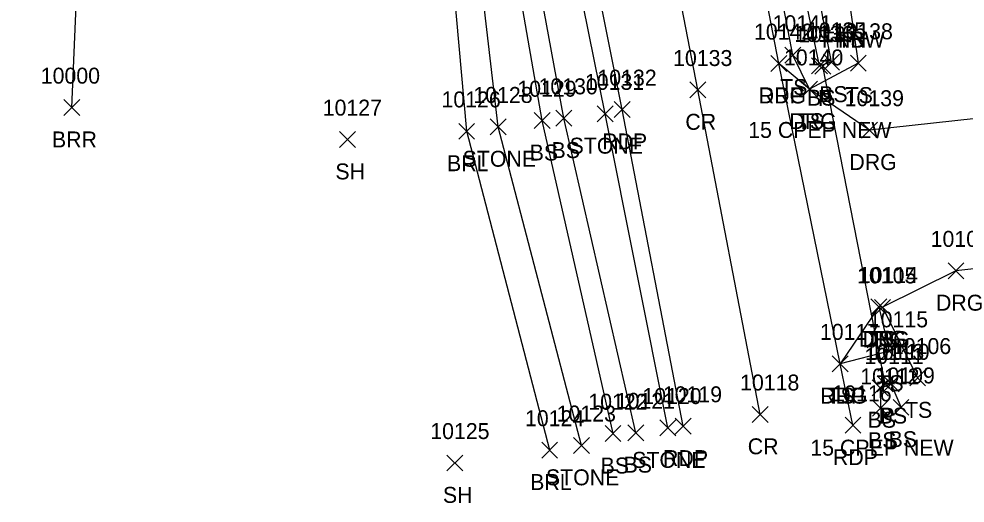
# Model space of a CAD drawing. Extents: x 1475671 to 1477951, y 592661 to 593821.
# Drawn here: x 1476843.4 to 1476962.1, y 592661.2 to 592721.9 of the extents above; entities that cross this region are included whole.
import ezdxf

# ---------------------------------------------------------------- set-up
doc = ezdxf.new("R2010")
doc.units = 0
for name, color, linetype in [('D_A', 7, 'Continuous'), ('D_C', 7, 'Continuous'), ('D_I', 7, 'Continuous'), ('D_TIC', 7, 'Continuous'), ('DCP', 7, 'Continuous'), ('L_A', 7, 'Continuous'), ('L_I', 7, 'Continuous'), ('L_TIC', 7, 'Continuous'), ('LABL', 7, 'Continuous'), ('LASF', 7, 'Continuous'), ('LELB', 7, 'Continuous'), ('P_A', 7, 'Continuous'), ('P_I', 7, 'Continuous'), ('P_TIC', 7, 'Continuous'), ('PET', 7, 'Continuous'), ('PRC', 7, 'Continuous'), ('R_A', 7, 'Continuous'), ('R_I', 7, 'Continuous'), ('R_TIC', 7, 'Continuous'), ('RDG', 7, 'Continuous')]:
    doc.layers.add(name, color=color, linetype=linetype)

msp = doc.modelspace()

# ---------------------------------------------------------------- linework, layer by layer
at = {"layer": 'D_TIC'}
for points in [[(1476943.28, 592715), (1476945.28, 592717)], [(1476945.28, 592715), (1476943.28, 592717)], [(1476951.09, 592675.16), (1476953.09, 592677.16)], [(1476953.09, 592675.16), (1476951.09, 592677.16)]]:
    msp.add_lwpolyline(points, dxfattribs=at)
at = {"layer": 'DCP'}
msp.add_lwpolyline([(1476952.09, 592676.16), (1476944.28, 592716)], dxfattribs=at)
at = {"layer": 'L_TIC'}
for points in [[(1476939.5, 592716.38), (1476941.5, 592718.38)], [(1476941.5, 592716.38), (1476939.5, 592718.38)], [(1476944.37, 592715.49), (1476946.37, 592717.49)], [(1476946.37, 592715.49), (1476944.37, 592717.49)], [(1476944.37, 592715.49), (1476946.37, 592717.49)], [(1476946.37, 592715.49), (1476944.37, 592717.49)], [(1476947.72, 592715.37), (1476949.72, 592717.37)], [(1476949.72, 592715.37), (1476947.72, 592717.37)], [(1476942.84, 592715.05), (1476944.84, 592717.05)], [(1476944.84, 592715.05), (1476942.84, 592717.05)], [(1476941.58, 592712.1), (1476943.58, 592714.1)], [(1476943.58, 592712.1), (1476941.58, 592714.1)], [(1476849.01, 592709.81), (1476851.01, 592711.81)], [(1476851.01, 592709.81), (1476849.01, 592711.81)], [(1476908.03, 592708.17), (1476910.03, 592710.17)], [(1476910.03, 592708.17), (1476908.03, 592710.17)], [(1476910.77, 592708.47), (1476912.77, 592710.47)], [(1476912.77, 592708.47), (1476910.77, 592710.47)], [(1476915.94, 592709.03), (1476917.94, 592711.03)], [(1476917.94, 592709.03), (1476915.94, 592711.03)], [(1476902.51, 592707.39), (1476904.51, 592709.39)], [(1476904.51, 592707.39), (1476902.51, 592709.39)], [(1476883.6, 592705.8), (1476885.6, 592707.8)], [(1476885.6, 592705.8), (1476883.6, 592707.8)], [(1476898.56, 592706.83), (1476900.56, 592708.83)], [(1476900.56, 592706.83), (1476898.56, 592708.83)], [(1476950.31, 592684.81), (1476952.31, 592686.81)], [(1476952.31, 592684.81), (1476950.31, 592686.81)], [(1476950.75, 592684.76), (1476952.75, 592686.76)], [(1476952.75, 592684.76), (1476950.75, 592686.76)], [(1476951.58, 592679.25), (1476953.58, 592681.25)], [(1476953.58, 592679.25), (1476951.58, 592681.25)], [(1476945.44, 592677.68), (1476947.44, 592679.68)], [(1476947.44, 592677.68), (1476945.44, 592679.68)], [(1476951.84, 592675.18), (1476953.84, 592677.18)], [(1476953.84, 592675.18), (1476951.84, 592677.18)], [(1476955.17, 592675.9), (1476957.17, 592677.9)], [(1476957.17, 592675.9), (1476955.17, 592677.9)], [(1476950.46, 592674.66), (1476952.46, 592676.66)], [(1476952.46, 592674.66), (1476950.46, 592676.66)], [(1476950.5, 592672.1), (1476952.5, 592674.1)], [(1476952.5, 592672.1), (1476950.5, 592674.1)], [(1476953.08, 592672.22), (1476955.08, 592674.22)], [(1476955.08, 592672.22), (1476953.08, 592674.22)], [(1476919.81, 592669.03), (1476921.81, 592671.03)], [(1476921.81, 592669.03), (1476919.81, 592671.03)], [(1476923.8, 592669.63), (1476925.8, 592671.63)], [(1476925.8, 592669.63), (1476923.8, 592671.63)], [(1476916.93, 592668.92), (1476918.93, 592670.92)], [(1476918.93, 592668.92), (1476916.93, 592670.92)], [(1476908.98, 592666.85), (1476910.98, 592668.85)], [(1476910.98, 592666.85), (1476908.98, 592668.85)], [(1476912.97, 592667.44), (1476914.97, 592669.44)], [(1476914.97, 592667.44), (1476912.97, 592669.44)], [(1476897.09, 592665.24), (1476899.09, 592667.24)], [(1476899.09, 592665.24), (1476897.09, 592667.24)]]:
    msp.add_lwpolyline(points, dxfattribs=at)
at = {"layer": 'LABL'}
for points in [[(1476850.01, 592710.81), (1476851.45, 592745.32), (1476850.04, 592796.99), (1476883.21, 592811.57)], [(1476909.98, 592667.85), (1476899.56, 592707.83), (1476895.4, 592754.41), (1476889.2, 592787.31), (1476883.21, 592811.57)]]:
    msp.add_lwpolyline(points, dxfattribs=at)
at = {"layer": 'LASF'}
for points in [[(1476924.8, 592670.63), (1476916.94, 592710.03), (1476907.96, 592754.45), (1476901.09, 592789.5), (1476894.98, 592818.12), (1476889.6, 592819.55), (1476884.72, 592817)], [(1476913.97, 592668.44), (1476903.51, 592708.39), (1476898.17, 592754.38), (1476891.27, 592788.22), (1476884.72, 592817)]]:
    msp.add_lwpolyline(points, dxfattribs=at)
at = {"layer": 'LELB'}
for points in [[(1476947.68, 592723.33), (1476948.72, 592716.37), (1476942.58, 592713.1), (1476940.5, 592717.38), (1476933.16, 592755.58), (1476925.3, 592796.65), (1476917.94, 592836.99), (1476905.66, 592899.26), (1476898.49, 592935.73), (1476888.52, 592980.9), (1476879.22, 593010.04), (1476868.24, 593047.6)], [(1476945.37, 592716.49), (1476943.84, 592716.05), (1476935.5, 592756.29), (1476927.52, 592796.97), (1476921.14, 592836.68), (1476908.22, 592899.62), (1476901.04, 592935.89), (1476890.97, 592981.04), (1476883.12, 593008.63), (1476873.18, 593048.38)], [(1476920.81, 592670.03), (1476911.77, 592709.47), (1476903.41, 592754.71), (1476895.75, 592788.73), (1476891.97, 592813.42), (1476891.84, 592816.89), (1476890.12, 592816.69), (1476888.99, 592813.17)], [(1476917.93, 592669.92), (1476909.03, 592709.17), (1476901.19, 592754.34), (1476894.06, 592787.7), (1476888.99, 592813.17)], [(1476945.37, 592716.49), (1476937.48, 592757.47), (1476930.6, 592798.25)], [(1476951.31, 592685.81), (1476952.58, 592680.25), (1476946.44, 592678.68)], [(1476951.75, 592685.76), (1476956.17, 592676.9)], [(1476954.08, 592673.22), (1476952.84, 592676.18), (1476951.46, 592675.66), (1476951.5, 592673.1)]]:
    msp.add_lwpolyline(points, dxfattribs=at)
at = {"layer": 'P_TIC'}
for points in [[(1476937.73, 592715.33), (1476939.73, 592717.33)], [(1476939.73, 592715.33), (1476937.73, 592717.33)], [(1476927.58, 592712.02), (1476929.58, 592714.02)], [(1476929.58, 592712.02), (1476927.58, 592714.02)], [(1476918.07, 592709.56), (1476920.07, 592711.56)], [(1476920.07, 592709.56), (1476918.07, 592711.56)], [(1476945.44, 592677.68), (1476947.44, 592679.68)], [(1476947.44, 592677.68), (1476945.44, 592679.68)], [(1476935.41, 592671.33), (1476937.41, 592673.33)], [(1476937.41, 592671.33), (1476935.41, 592673.33)], [(1476925.72, 592669.85), (1476927.72, 592671.85)], [(1476927.72, 592669.85), (1476925.72, 592671.85)], [(1476947.05, 592669.97), (1476949.05, 592671.97)], [(1476949.05, 592669.97), (1476947.05, 592671.97)]]:
    msp.add_lwpolyline(points, dxfattribs=at)
at = {"layer": 'PET'}
for points in [[(1476948.05, 592670.97), (1476946.44, 592678.68), (1476938.73, 592716.33), (1476931.28, 592754.87), (1476923.71, 592796.39), (1476916.31, 592836.87), (1476904.07, 592899.01), (1476897.02, 592935.82), (1476885.79, 592980.24), (1476877.69, 593009.63), (1476865.86, 593046.37), (1476861.23, 593059.8), (1476852.05, 593085.53)], [(1476926.72, 592670.85), (1476919.07, 592710.56), (1476910.29, 592754.48), (1476903.69, 592790.26), (1476898.6, 592819.47), (1476892.51, 592847.86), (1476883.56, 592895.28), (1476876.69, 592931.37), (1476866.39, 592975.94)]]:
    msp.add_lwpolyline(points, dxfattribs=at)
at = {"layer": 'PRC'}
msp.add_lwpolyline([(1476936.41, 592672.33), (1476928.58, 592713.02), (1476920.34, 592755.64), (1476913.25, 592793.06), (1476905.79, 592835.15), (1476893.85, 592896.99), (1476886.39, 592933.64), (1476875.73, 592978.34), (1476865.02, 593017.01), (1476853.41, 593046.52), (1476843.49, 593055.1), (1476828.74, 593067.47), (1476810.85, 593077.22), (1476783.7, 593084.94)], dxfattribs=at)
at = {"layer": 'R_TIC'}
for points in [[(1476937.73, 592715.33), (1476939.73, 592717.33)], [(1476939.73, 592715.33), (1476937.73, 592717.33)], [(1476941.58, 592712.1), (1476943.58, 592714.1)], [(1476943.58, 592712.1), (1476941.58, 592714.1)], [(1476949.12, 592706.98), (1476951.12, 592708.98)], [(1476951.12, 592706.98), (1476949.12, 592708.98)], [(1476959.98, 592689.34), (1476961.98, 592691.34)], [(1476961.98, 592689.34), (1476959.98, 592691.34)], [(1476950.31, 592684.81), (1476952.31, 592686.81)], [(1476952.31, 592684.81), (1476950.31, 592686.81)], [(1476950.75, 592684.76), (1476952.75, 592686.76)], [(1476952.75, 592684.76), (1476950.75, 592686.76)], [(1476945.44, 592677.68), (1476947.44, 592679.68)], [(1476947.44, 592677.68), (1476945.44, 592679.68)]]:
    msp.add_lwpolyline(points, dxfattribs=at)
at = {"layer": 'RDG'}
for points in [[(1477031.5, 592758.24), (1477007.65, 592728.93), (1476982.65, 592711.52), (1476950.12, 592707.98), (1476942.58, 592713.1), (1476938.73, 592716.33)], [(1477000.94, 592694.52), (1476984.42, 592692.93), (1476960.98, 592690.34), (1476951.75, 592685.76), (1476951.31, 592685.81), (1476946.44, 592678.68)]]:
    msp.add_lwpolyline(points, dxfattribs=at)

# ---------------------------------------------------------------- texts
at = {"layer": 'D_A'}
for p in [(1476943.66, 592711), (1476951.47, 592671.16)]:
    msp.add_text('P', height=2, dxfattribs=at).set_placement(p)
at = {"layer": 'D_C'}
for p in [(1476934.9, 592707), (1476942.7, 592667.16)]:
    msp.add_text('15 CPEP NEW', height=2, dxfattribs=at).set_placement(p)
at = {"layer": 'D_I'}
for s, p in [('10137', (1476941.18, 592719)), ('10113', (1476949.55, 592679.16))]:
    msp.add_text(s, height=2, dxfattribs=at).set_placement(p)
at = {"layer": 'L_A'}
for s, p in [('FNBW', (1476944.15, 592718.33)), ('TS', (1476946.09, 592718.33)), ('FN', (1476946.16, 592718.33)), ('TS', (1476938.91, 592712.38)), ('BS', (1476942.28, 592711.05)), ('BS', (1476943.81, 592711.49)), ('BS', (1476943.81, 592711.49)), ('TS', (1476947.13, 592711.37)), ('TS', (1476940.99, 592708.1)), ('BRR', (1476847.5, 592705.81)), ('STONE', (1476912.48, 592705.03)), ('STONE', (1476899.05, 592703.39)), ('BS', (1476907.47, 592704.17)), ('BS', (1476910.21, 592704.47)), ('BRL', (1476897.1, 592702.83)), ('SH', (1476883.08, 592701.8)), ('TS', (1476949.72, 592680.81)), ('TS', (1476950.16, 592680.76)), ('TS', (1476950.99, 592675.25)), ('TS', (1476944.85, 592673.68)), ('TS', (1476954.58, 592671.9)), ('BS', (1476949.9, 592670.66)), ('BS', (1476951.28, 592671.18)), ('BS', (1476949.94, 592668.1)), ('BS', (1476952.52, 592668.22)), ('STONE', (1476920.34, 592665.63)), ('BS', (1476916.37, 592664.92)), ('BS', (1476919.25, 592665.03)), ('STONE', (1476909.51, 592663.44)), ('BRL', (1476907.53, 592662.85)), ('SH', (1476896.58, 592661.24))]:
    msp.add_text(s, height=2, dxfattribs=at).set_placement(p)
at = {"layer": 'L_I'}
for s, p in [('10141', (1476937.96, 592720.38)), ('10136', (1476940.68, 592719.05)), ('10135', (1476942.27, 592719.49)), ('10135', (1476942.27, 592719.49)), ('10138', (1476945.62, 592719.37)), ('10140', (1476939.39, 592716.1)), ('10000', (1476846.1, 592713.81)), ('10131', (1476914.4, 592713.03)), ('10129', (1476905.92, 592712.17)), ('10130', (1476908.58, 592712.47)), ('10126', (1476896.4, 592710.83)), ('10128', (1476900.4, 592711.39)), ('10127', (1476881.49, 592709.8)), ('10105', (1476948.57, 592688.76)), ('10114', (1476948.77, 592688.81)), ('10115', (1476950.04, 592683.25)), ('10117', (1476943.9, 592681.68)), ('10106', (1476952.94, 592679.9)), ('10111', (1476949.49, 592678.66)), ('10110', (1476950.22, 592679.18)), ('10112', (1476948.96, 592676.1)), ('10109', (1476950.89, 592676.22)), ('10122', (1476914.83, 592672.92)), ('10121', (1476918.27, 592673.03)), ('10120', (1476921.61, 592673.63)), ('10123', (1476910.86, 592671.44)), ('10124', (1476906.88, 592670.85)), ('10125', (1476894.99, 592669.24))]:
    msp.add_text(s, height=2, dxfattribs=at).set_placement(p)
at = {"layer": 'P_A'}
for s, p in [('RDP', (1476936.22, 592711.33)), ('CR', (1476927.01, 592708.02)), ('RDP', (1476916.56, 592705.56)), ('RDP', (1476943.93, 592673.68)), ('CR', (1476934.84, 592667.33)), ('RDP', (1476924.21, 592665.85)), ('RDP', (1476945.54, 592665.97))]:
    msp.add_text(s, height=2, dxfattribs=at).set_placement(p)
at = {"layer": 'P_I'}
for s, p in [('10142', (1476935.63, 592719.33)), ('10133', (1476925.47, 592716.02)), ('10132', (1476915.97, 592713.56)), ('10117', (1476943.9, 592681.68)), ('10118', (1476933.88, 592675.33)), ('10119', (1476924.18, 592673.85)), ('10116', (1476945.46, 592673.97))]:
    msp.add_text(s, height=2, dxfattribs=at).set_placement(p)
at = {"layer": 'R_A'}
for p in [(1476936.22, 592711.33), (1476940.07, 592708.1), (1476947.6, 592702.98), (1476958.47, 592685.34), (1476948.8, 592680.81), (1476949.24, 592680.76), (1476943.93, 592673.68)]:
    msp.add_text('DRG', height=2, dxfattribs=at).set_placement(p)
at = {"layer": 'R_I'}
for s, p in [('10142', (1476935.63, 592719.33)), ('10140', (1476939.39, 592716.1)), ('10139', (1476947.01, 592710.98)), ('10104', (1476957.8, 592693.34)), ('10105', (1476948.57, 592688.76)), ('10114', (1476948.77, 592688.81)), ('10117', (1476943.9, 592681.68))]:
    msp.add_text(s, height=2, dxfattribs=at).set_placement(p)

doc.saveas('drawing.dxf')
